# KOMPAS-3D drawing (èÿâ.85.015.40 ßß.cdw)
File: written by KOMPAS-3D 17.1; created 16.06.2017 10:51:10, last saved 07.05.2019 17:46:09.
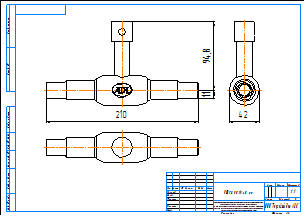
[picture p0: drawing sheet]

Sheet 1: A3, landscape

Title block, sheet 1: name: КШГ.85.015.40 сс; material: Внимание! Данный продукт является объектом авторского права ООО «Торговый Дом АДЛ». / Запрещается изменение, копирование, распространение / (в том числе путем копирования на другие сайты и ресурсы в Интернете) / или любое иное использование информации и объектов без предварительного / согласия правообладателя (ООО «Торговый Дом АДЛ»).; scale: 1:1; sheets: 1; organisation: ООО "Торговый дом АДЛ"; sheet format: A3; stored path: C:\Users\tra\Desktop\2д чертежи\Шаровые краны БИВАЛ\КШ_Бивал_серия_82_85\KOMPAS 2D\КШГ.85.015.40 сс.cdw

Views: Спереди 1, Проекционный вид 2, Проекционный вид 3
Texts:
  Klimkovich
  ADL
Dimensions and other numbers on the sheet: 210; 94,8; 11; 42; 1:1; 1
